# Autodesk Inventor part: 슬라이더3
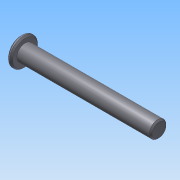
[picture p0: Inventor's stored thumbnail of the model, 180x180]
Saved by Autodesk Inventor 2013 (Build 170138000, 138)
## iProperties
Company: 한국ATC센터
Created: 2015-04
Part Number: 슬라이더3
Document SubType Name: Modeling
Designer: KYOUNG IL JANG
Density: 7.85 g/cm^3
Material: 강
Mass: 92.8999 g
Surface Area: 43.7403 cm^2
Volume: 11.8344 cm^3
Author: KYOUNG IL JANG
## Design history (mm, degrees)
sketch "스케치1"
  geometry: L1 (0, 0)-(0, 10); L2 (0, 10)-(-3, 10); L3 (-3, 10)-(-3, 6); L4 (-3, 6)-(-100, 6); L5 (-100, 6)-(-100, 0); L6 (-100, 0)-(0, 0)
  constraints: 12 end point, 4 parallel, 1 perpendicular, 1 vertical
  dimensions: "d0" = 12 diameter of L4 L6; "d1" = 20 diameter of L2 L6; "d2" = 3 distance between parallel lines of L3 L1; "d3" = 100 distance between parallel lines of L5 L1
revolve "회전1" sketch "스케치1" stored, may be unused: angle "d4" = 90 deg
chamfer "모따기1" distance "d5" = 1; stored, may be unused: second distance "d6" = 2, angle "d7" = 45 deg
node "솔리드1"
